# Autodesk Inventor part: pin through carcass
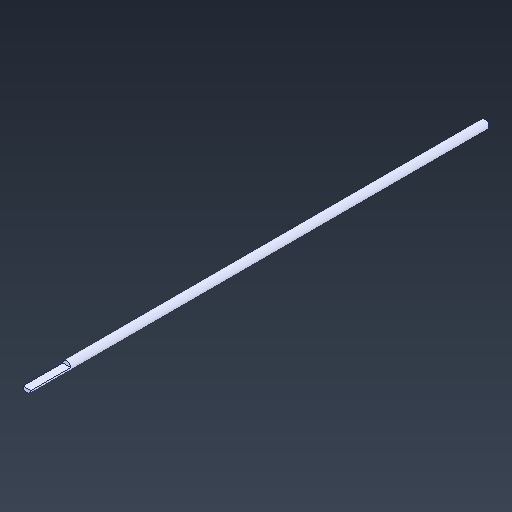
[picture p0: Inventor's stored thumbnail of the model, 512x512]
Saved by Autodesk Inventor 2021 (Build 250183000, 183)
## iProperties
Created: 2020-06
Part Number: pin through carcass
Material: SOLIDWORKS Materials|1060 Alloy
Document SubType Name: Modeling
Designer: ftrauzettel
Density: 2.7 g/cm^3
Appearance: 202,209,238
Author: ftrauzettel
Sending System: SolidWorks 2016
Last Author: Pam
Last Saved: 2020-10-15
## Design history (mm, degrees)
feature "Boss-Extrude2"
body "Solid1"
